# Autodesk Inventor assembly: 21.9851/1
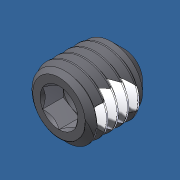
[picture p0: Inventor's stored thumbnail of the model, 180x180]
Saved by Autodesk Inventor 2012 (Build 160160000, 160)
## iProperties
Created: 2014-01
Part Number: 21.9851/1
Document SubType Name: Assembly
Designer: Admin
Vendor: S
Description: M5X5 SET SCREW THREAD LOCK SS
Translation Standard: STEP AP203
FileName: 90251A162.step
PreProcessor: SolidWorks 2012
PostProcessor: Build: 160, Release: 2012 RTM - Date: Tue 03/01/2011
Sent Units: inch
Uncertainty: 1e-05
Author: Admin
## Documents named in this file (3)
- C:\Andys Backup Data\ANDY'S INVENTOR\INVENTOR LIBRARIES\PARTS LIBRARY\FASTENING ELEMENTS\SET SCREWS\21.9851_1 M5X5 SET SCREW THREAD LOCK SS.iam
- C:\Andys Backup Data\ANDY'S INVENTOR\INVENTOR LIBRARIES\PARTS LIBRARY\FASTENING ELEMENTS\SET SCREWS\SUBCOMPONENTS\21.9851_1 THREAD LOCK.ipt
- C:\Andys Backup Data\ANDY'S INVENTOR\INVENTOR LIBRARIES\PARTS LIBRARY\FASTENING ELEMENTS\SET SCREWS\SUBCOMPONENTS\21.9851_1 M5X5 SET SCREW SS.ipt
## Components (2 placed, 2 different names)
1. 21.9851_1 THREAD LOCK:1
2. 21.9851_1 M5X5 SET SCREW SS:1
